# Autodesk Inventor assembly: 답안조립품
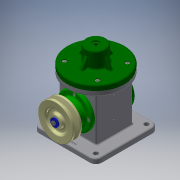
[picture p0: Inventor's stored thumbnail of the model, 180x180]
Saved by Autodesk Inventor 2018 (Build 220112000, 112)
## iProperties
Created: 2021-05
Part Number: 답안조립품
Document SubType Name: Assembly
Designer: 1class6
Author: 1class6
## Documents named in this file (19)
- C:\Users\1class6\Desktop\710506V1021\답안조립품.iam
- C:\Users\1class6\Desktop\710506V1021\본체.ipt
- C:\Users\1class6\Desktop\710506V1021\E-링.ipt
- C:\Users\1class6\Desktop\710506V1021\V-벨트풀리.ipt
- C:\Users\1class6\Desktop\710506V1021\덮개.ipt
- C:\Users\1class6\Desktop\710506V1021\뒤커버.ipt
- C:\Users\1class6\Desktop\710506V1021\링크.ipt
- C:\Users\1class6\Desktop\710506V1021\베어링 17 x 40 x 12.ipt
- C:\Users\1class6\Desktop\710506V1021\볼트 M4 x 10.ipt
- C:\Users\1class6\Desktop\710506V1021\볼트 M4 x 12.ipt
- 볼트 M4 x 12.ipt
- C:\Users\1class6\Desktop\710506V1021\슬라이더.ipt
- C:\Users\1class6\Desktop\710506V1021\앞커버.ipt
- C:\Users\1class6\Desktop\710506V1021\오일 실 17 30 8.ipt
- C:\Users\1class6\Desktop\710506V1021\와셔 4x16.ipt
- C:\Users\1class6\Desktop\710506V1021\클레비스 핀 6 x 22.ipt
- 클레비스 핀 6 x 22.ipt
- C:\Users\1class6\Desktop\710506V1021\키 4 x 4 x 12.ipt
- C:\Users\1class6\Desktop\710506V1021\편심축.ipt
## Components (2 placed, 2 different names)
1. E-링:1
2. V-벨트풀리:1 — 각도:2
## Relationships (1: Angle 1)
- 각도:2 [Angle]: V-벨트풀리:1
